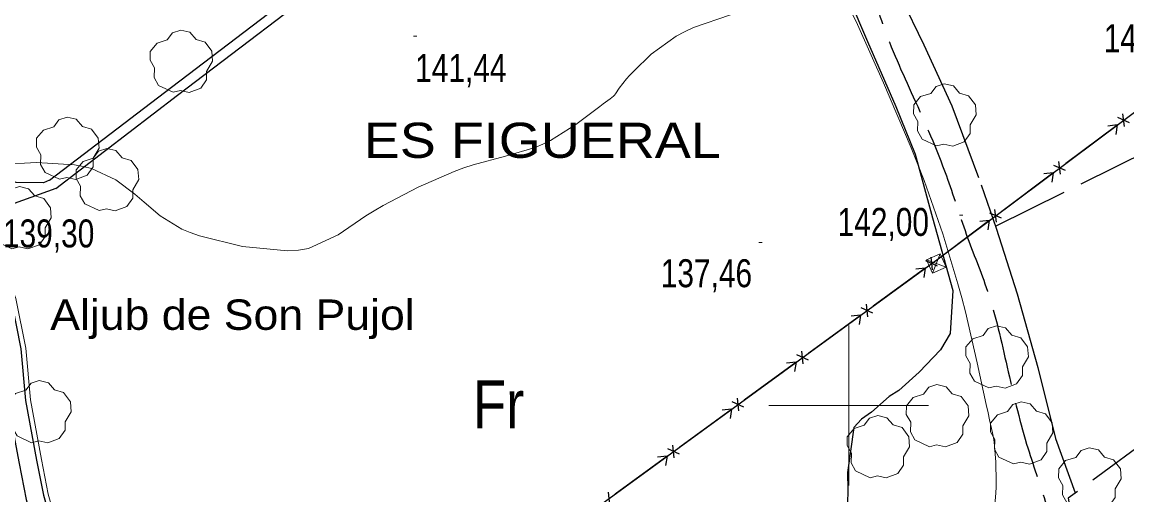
# Model space of a CAD drawing. Extents: x -807245 to 6129983, y -54972206 to 262146364.
# Drawn here: x 488741 to 489087.2, y 4383472 to 4383619.9 of the extents above; entities that cross this region are included whole.
import ezdxf
from ezdxf.enums import TextEntityAlignment as Align

# ---------------------------------------------------------------- set-up
doc = ezdxf.new("R2010")
doc.units = 0
doc.header["$LTSCALE"] = 4
doc.linetypes.add('LONG_DASHED', pattern=[7.5, 6, -1.5])
for name, color, linetype, lineweight in [('1', 7, 'Continuous', 13), ('25', 7, 'LONG_DASHED', 25), ('27', 7, 'Continuous', 25), ('29', 7, 'Continuous', 13), ('36', 7, 'Continuous', 25), ('38', 7, 'Continuous', 25), ('43', 7, 'Continuous', 25), ('51', 7, 'Continuous', 13), ('7', 7, 'Continuous', 13), ('9', 7, 'Continuous', 13)]:
    doc.layers.add(name, color=color, linetype=linetype, lineweight=lineweight)
doc.layers.add('31', color=7, linetype='Continuous')
doc.layers.add('5', color=7, linetype='Continuous')

msp = doc.modelspace()

# ---------------------------------------------------------------- linework, layer by layer
at = {"layer": '1'}
for p, q in [((489000, 4383525), (489000, 4383475)), ((488975, 4383500), (489025, 4383500))]:
    msp.add_line(p, q, dxfattribs=at)
at = {"layer": '25'}
msp.add_line((489045.94, 4383556.09), (489152.62, 4383608.65), dxfattribs=at)
for points in [[(489064.84, 4383687.92), (489050.6, 4383701.9), (489044.09, 4383702.72), (489041.35, 4383706.35), (489037.89, 4383712.32), (489035.25, 4383717.83), (489031.19, 4383723.35), (488971.86, 4383711.2), (488971.58, 4383706.47), (488982.99, 4383687.44), (488994.03, 4383668.18), (489007.57, 4383645.07), (489016.3, 4383627.79), (489023.56, 4383612.78), (489032.27, 4383593.77), (489041.51, 4383568.99), (489046.16, 4383555.43), (489052.75, 4383534.95), (489059.24, 4383511.84), (489064.77, 4383489.72), (489070.99, 4383472.64)], [(488997.32, 4383634.23), (489005.86, 4383613.88), (489014.71, 4383593.52), (489020.84, 4383578.6), (489026.24, 4383558.66), (489032.66, 4383536), (489031.76, 4383522.51), (489028.77, 4383517.44), (489022.02, 4383510.47), (489015.72, 4383504.69), (489012.63, 4383502.77), (489007.17, 4383497.88), (489003.99, 4383495.67), (489001.56, 4383493.07), (488999.6, 4383479.06), (488999.69, 4383473.74), (488999.64, 4383469.08), (488999.45, 4383465.86), (488999.4, 4383461.28), (489002.78, 4383448.12), (489005.3, 4383445.61), (489006.19, 4383444.78), (489011.29, 4383437.82), (489016.89, 4383429.35)], [(489240.47, 4383481.68), (489167.79, 4383431.69), (489119.98, 4383508.68), (489068.76, 4383471), (489070.95, 4383459.27), (489077.91, 4383424.98), (489081.71, 4383402.66), (489085.82, 4383375.15), (489086.67, 4383350.61), (489087.73, 4383318.64), (489087.36, 4383306.34), (489106.74, 4383317.1)]]:
    msp.add_lwpolyline(points, dxfattribs=at)
at = {"layer": '27'}
msp.add_spline([(491255.21, 4383970.03), (491244.34, 4383967.52), (491230.36, 4383957.66), (491230.81, 4383957.81), (491230.81, 4383957.81), (491220.15, 4383951.47), (491212.7, 4383943.01), (491205.06, 4383944.23), (491184.85, 4383957.71), (491152.82, 4383981.27), (491128.36, 4384004.58), (491128.29, 4384004.88), (491122.26, 4384021.39), (491095.75, 4384034.59), (491071.07, 4384059.32), (491064.71, 4384065.12)], degree=3, dxfattribs=at)
at = {"layer": '29'}
for points in [[(488788.32, 4383597.98), (488783.78, 4383600.1), (488782.37, 4383602.64), (488782.47, 4383605.62), (488781.1, 4383608.03), (488781.14, 4383610.78), (488783.3, 4383613.38), (488786.49, 4383614.38), (488788.14, 4383616.57), (488790.71, 4383617.4), (488793.57, 4383616.75), (488795.52, 4383614.48), (488798.33, 4383613.66), (488800.46, 4383610.81), (488800.7, 4383607.68), (488798.82, 4383604.53), (488798.82, 4383601.85), (488797, 4383599.24), (488793.38, 4383597.9), (488790.61, 4383598.53)], [(489027.53, 4383581.23), (489022.99, 4383583.35), (489021.58, 4383585.89), (489021.68, 4383588.87), (489020.31, 4383591.28), (489020.35, 4383594.03), (489022.51, 4383596.63), (489025.7, 4383597.63), (489027.35, 4383599.82), (489029.92, 4383600.65), (489032.78, 4383600), (489034.73, 4383597.73), (489037.54, 4383596.91), (489039.67, 4383594.06), (489039.91, 4383590.93), (489038.03, 4383587.78), (489038.03, 4383585.1), (489036.21, 4383582.49), (489032.59, 4383581.15), (489029.82, 4383581.78)], [(488752.75, 4383570.78), (488748.21, 4383572.9), (488746.8, 4383575.44), (488746.9, 4383578.42), (488745.53, 4383580.83), (488745.57, 4383583.58), (488747.73, 4383586.18), (488750.92, 4383587.18), (488752.57, 4383589.37), (488755.14, 4383590.2), (488758, 4383589.55), (488759.95, 4383587.28), (488762.76, 4383586.46), (488764.89, 4383583.61), (488765.13, 4383580.48), (488763.25, 4383577.33), (488763.25, 4383574.65), (488761.43, 4383572.04), (488757.81, 4383570.7), (488755.04, 4383571.33)], [(488765.17, 4383560.96), (488760.63, 4383563.08), (488759.22, 4383565.62), (488759.32, 4383568.6), (488757.95, 4383571.01), (488757.99, 4383573.76), (488760.15, 4383576.36), (488763.34, 4383577.36), (488764.99, 4383579.55), (488767.56, 4383580.38), (488770.42, 4383579.73), (488772.37, 4383577.46), (488775.18, 4383576.64), (488777.31, 4383573.79), (488777.55, 4383570.66), (488775.67, 4383567.51), (488775.67, 4383564.83), (488773.85, 4383562.22), (488770.23, 4383560.88), (488767.46, 4383561.51)], [(488737.8, 4383549.04), (488733.26, 4383551.16), (488731.85, 4383553.7), (488731.95, 4383556.68), (488730.58, 4383559.09), (488730.62, 4383561.84), (488732.78, 4383564.44), (488735.97, 4383565.44), (488737.62, 4383567.63), (488740.19, 4383568.46), (488743.05, 4383567.81), (488745, 4383565.54), (488747.81, 4383564.72), (488749.94, 4383561.87), (488750.18, 4383558.74), (488748.3, 4383555.59), (488748.3, 4383552.91), (488746.48, 4383550.3), (488742.86, 4383548.96), (488740.09, 4383549.59)], [(489043.92, 4383505.5), (489039.38, 4383507.62), (489037.97, 4383510.16), (489038.07, 4383513.14), (489036.7, 4383515.55), (489036.74, 4383518.3), (489038.9, 4383520.9), (489042.09, 4383521.9), (489043.74, 4383524.09), (489046.31, 4383524.92), (489049.17, 4383524.27), (489051.12, 4383522), (489053.93, 4383521.18), (489056.06, 4383518.33), (489056.3, 4383515.2), (489054.42, 4383512.05), (489054.42, 4383509.37), (489052.6, 4383506.76), (489048.98, 4383505.42), (489046.21, 4383506.05)], [(488744.01, 4383488.36), (488739.47, 4383490.48), (488738.06, 4383493.02), (488738.16, 4383496), (488736.79, 4383498.41), (488736.83, 4383501.16), (488738.99, 4383503.76), (488742.18, 4383504.76), (488743.83, 4383506.95), (488746.4, 4383507.78), (488749.26, 4383507.13), (488751.21, 4383504.86), (488754.02, 4383504.04), (488756.15, 4383501.19), (488756.39, 4383498.06), (488754.51, 4383494.91), (488754.51, 4383492.23), (488752.69, 4383489.62), (488749.07, 4383488.28), (488746.3, 4383488.91)], [(489025.26, 4383487.11), (489020.72, 4383489.23), (489019.31, 4383491.77), (489019.41, 4383494.75), (489018.04, 4383497.16), (489018.08, 4383499.91), (489020.24, 4383502.51), (489023.43, 4383503.51), (489025.08, 4383505.7), (489027.65, 4383506.53), (489030.51, 4383505.88), (489032.46, 4383503.61), (489035.27, 4383502.79), (489037.4, 4383499.94), (489037.64, 4383496.81), (489035.76, 4383493.66), (489035.76, 4383490.98), (489033.94, 4383488.37), (489030.32, 4383487.03), (489027.55, 4383487.66)], [(489051.6, 4383481.7), (489047.06, 4383483.82), (489045.65, 4383486.36), (489045.75, 4383489.34), (489044.38, 4383491.75), (489044.42, 4383494.5), (489046.58, 4383497.1), (489049.77, 4383498.1), (489051.42, 4383500.29), (489053.99, 4383501.12), (489056.85, 4383500.47), (489058.8, 4383498.2), (489061.61, 4383497.38), (489063.74, 4383494.53), (489063.98, 4383491.4), (489062.1, 4383488.25), (489062.1, 4383485.57), (489060.28, 4383482.96), (489056.66, 4383481.62), (489053.89, 4383482.25)], [(489006.69, 4383477.41), (489002.15, 4383479.53), (489000.74, 4383482.07), (489000.84, 4383485.05), (488999.47, 4383487.46), (488999.51, 4383490.21), (489001.67, 4383492.81), (489004.86, 4383493.81), (489006.51, 4383496), (489009.08, 4383496.83), (489011.94, 4383496.18), (489013.89, 4383493.91), (489016.7, 4383493.09), (489018.83, 4383490.24), (489019.07, 4383487.11), (489017.19, 4383483.96), (489017.19, 4383481.28), (489015.37, 4383478.67), (489011.75, 4383477.33), (489008.98, 4383477.96)], [(489072.97, 4383467.36), (489068.43, 4383469.48), (489067.02, 4383472.02), (489067.12, 4383475), (489065.75, 4383477.41), (489065.79, 4383480.16), (489067.95, 4383482.76), (489071.14, 4383483.76), (489072.79, 4383485.95), (489075.36, 4383486.78), (489078.22, 4383486.13), (489080.17, 4383483.86), (489082.98, 4383483.04), (489085.11, 4383480.19), (489085.35, 4383477.06), (489083.47, 4383473.91), (489083.47, 4383471.23), (489081.65, 4383468.62), (489078.03, 4383467.28), (489075.26, 4383467.91)]]:
    msp.add_lwpolyline(points, close=True, dxfattribs=at)
at = {"layer": '36'}
for points in [[(488701.67, 4383601.03), (488713.18, 4383583.78), (488720.76, 4383571.83), (488727.27, 4383559.98), (488731.21, 4383549.93), (488737.55, 4383533.06), (488740.6, 4383517.68), (488742.06, 4383501.51), (488745.58, 4383482.85), (488747.68, 4383471.91), (488751.03, 4383460.11), (488755.94, 4383445.19), (488763.36, 4383423.37), (488769.52, 4383401.51), (488775.12, 4383378.28), (488779.4, 4383360.18), (488784.4, 4383341.28), (488787.42, 4383323.42), (488790.51, 4383309.68), (488792.66, 4383293.05), (488794.73, 4383278.89), (488796.8, 4383269.66)], [(488697.56, 4383598.21), (488708.51, 4383580.77), (488715.97, 4383569), (488722.23, 4383557.62), (488726.02, 4383547.94), (488732.19, 4383531.54), (488735.09, 4383516.88), (488736.55, 4383500.75), (488740.12, 4383481.81), (488742.27, 4383470.62), (488745.71, 4383458.48), (488750.67, 4383443.42), (488758.05, 4383421.72), (488764.14, 4383400.1), (488769.72, 4383376.99), (488774.01, 4383358.83), (488778.96, 4383340.1), (488781.97, 4383322.35), (488785.03, 4383308.71), (488787.15, 4383292.29), (488789.26, 4383277.88), (488791.34, 4383268.61)]]:
    msp.add_lwpolyline(points, dxfattribs=at)
at = {"layer": '38'}
msp.add_line((488751.62, 4383567.92), (488727.54, 4383559.3), dxfattribs=at)
for points in [[(488751.62, 4383567.92), (488789.76, 4383597.05), (488843.03, 4383637.6), (488887.89, 4383679.96), (488895.08, 4383687.46), (488898.54, 4383694.17), (488901.86, 4383699.2), (488905.38, 4383705.28), (488906.3, 4383707.26), (488907.87, 4383708.98), (488910.28, 4383710.27), (488911.71, 4383710.66), (488914.41, 4383711.57), (488928.26, 4383713.8), (488964.77, 4383720.59), (489019.58, 4383732.51), (489043.43, 4383738.69), (489051.39, 4383740.35), (489055.38, 4383740.31), (489059.3, 4383739.22), (489062.91, 4383737.71), (489067.01, 4383734.96), (489070.32, 4383730.1)], [(488749.66, 4383570.48), (488787.8, 4383599.61), (488840.94, 4383640.07), (488885.62, 4383682.25), (488892.43, 4383689.35), (488895.75, 4383695.8), (488899.12, 4383700.9), (488902.52, 4383706.76), (488903.58, 4383709.06), (488905.86, 4383711.56), (488909.08, 4383713.29), (488910.77, 4383713.75), (488913.63, 4383714.71), (488927.71, 4383716.98), (488952.22, 4383721.54)], [(488749.66, 4383570.48), (488747.74, 4383569.7), (488739.18, 4383569.8), (488734.92, 4383571.12), (488726.18, 4383574.08), (488721.92, 4383575.62), (488715.87, 4383579.53)]]:
    msp.add_lwpolyline(points, dxfattribs=at)
at = {"layer": '38', "linetype": 'LONG_DASHED'}
msp.add_spline([(488955.84, 4383718.93), (488982.19, 4383676.49), (488994.16, 4383653.7), (489004.69, 4383635.88), (489010.58, 4383619.45), (489020.22, 4383596.54), (489030.59, 4383571.89), (489036.84, 4383553.59), (489043.46, 4383535.81), (489049.64, 4383512.03), (489055.75, 4383487.95), (489061.98, 4383468.82), (489067.02, 4383449.79), (489070.82, 4383428.51), (489074.72, 4383407.91), (489078.13, 4383385.07), (489080.63, 4383367.11), (489082.86, 4383338.57), (489084.43, 4383298.57), (489086.67, 4383251.81), (489090.1, 4383204.28), (489089.96, 4383184.77)], degree=3, dxfattribs=at)
at = {"layer": '43'}
for p, q in [((489087.96, 4383588.47), (489084.29, 4383590.05)), ((489086.36, 4383587.27), (489085.89, 4383591.24)), ((489068, 4383575.76), (489084.03, 4383587.72)), ((489084.12, 4383587.77), (489081.14, 4383587.42)), ((489084.12, 4383587.77), (489083.68, 4383584.81)), ((489067.92, 4383573.52), (489064.25, 4383575.1)), ((489066.32, 4383572.33), (489065.85, 4383576.3)), ((489047.96, 4383560.81), (489063.99, 4383572.77)), ((489064.08, 4383572.83), (489061.1, 4383572.47)), ((489064.08, 4383572.83), (489063.64, 4383569.86)), ((489046.28, 4383557.38), (489045.81, 4383561.35)), ((489044.04, 4383557.88), (489041.06, 4383557.53)), ((489044.04, 4383557.88), (489043.61, 4383554.91)), ((489047.88, 4383558.58), (489044.21, 4383560.15)), ((489026.2, 4383542.46), (489025.78, 4383546.43)), ((489007.7, 4383531.15), (489023.87, 4383542.92)), ((489023.96, 4383542.98), (489020.98, 4383542.66)), ((489023.96, 4383542.98), (489023.49, 4383540.02)), ((489027.82, 4383543.63), (489024.16, 4383545.25)), ((489007.6, 4383528.93), (489003.95, 4383530.55)), ((489005.98, 4383527.75), (489005.56, 4383531.72)), ((488987.49, 4383516.45), (489003.66, 4383528.21)), ((489003.74, 4383528.27), (489000.76, 4383527.96)), ((489003.74, 4383528.27), (489003.28, 4383525.31)), ((488987.38, 4383514.22), (488983.73, 4383515.84)), ((488985.76, 4383513.04), (488985.35, 4383517.02)), ((488967.28, 4383501.75), (488983.45, 4383513.51)), ((488983.53, 4383513.57), (488980.54, 4383513.25)), ((488983.53, 4383513.57), (488983.06, 4383510.61)), ((488965.55, 4383498.34), (488965.13, 4383502.31)), ((488947.07, 4383487.05), (488963.24, 4383498.81)), ((488963.31, 4383498.86), (488960.33, 4383498.55)), ((488963.31, 4383498.86), (488962.84, 4383495.9)), ((488967.16, 4383499.51), (488963.51, 4383501.14)), ((488945.33, 4383483.63), (488944.91, 4383487.61)), ((488926.86, 4383472.35), (488943.03, 4383484.11)), ((488943.09, 4383484.16), (488940.11, 4383483.84)), ((488943.09, 4383484.16), (488942.63, 4383481.19)), ((488946.95, 4383484.81), (488943.29, 4383486.43)), ((488925.11, 4383468.92), (488924.69, 4383472.9))]:
    msp.add_line(p, q, dxfattribs=at)
at = {"layer": '43', "lineweight": 13}
for p, q in [((489026.21, 4383541.42), (489028.69, 4383547.44)), ((489024.39, 4383545.54), (489030.51, 4383543.32))]:
    msp.add_line(p, q, dxfattribs=at)
at = {"layer": '43'}
for points in [[(488001.89, 4382789.17), (488218.68, 4382951.32), (488457.31, 4383127.02), (488717.97, 4383320.4), (489027.99, 4383545.91), (489266.87, 4383724.08), (489744.68, 4384077.94)], [(489027.92, 4383545.86), (489027.99, 4383545.91), (489043.95, 4383557.82)]]:
    msp.add_lwpolyline(points, dxfattribs=at)
at = {"layer": '43', "lineweight": 13}
msp.add_lwpolyline([(489026.21, 4383541.42), (489024.39, 4383545.54), (489028.69, 4383547.44), (489030.51, 4383543.32)], close=True, dxfattribs=at)
at = {"layer": '51'}
msp.add_lwpolyline([(488731.39, 4383553.76), (488732.67, 4383550.49), (488739.06, 4383533.49), (488742.15, 4383517.9), (488743.61, 4383501.73), (488747.12, 4383483.14), (488749.2, 4383472.27), (488752.53, 4383460.57), (488757.42, 4383445.69), (488764.86, 4383423.83), (488771.03, 4383401.91), (488776.64, 4383378.64), (488780.92, 4383360.56), (488785.93, 4383341.61), (488788.96, 4383323.72), (488792.05, 4383309.95), (488794.21, 4383293.26), (488796.27, 4383279.17), (488798.34, 4383269.95)], dxfattribs=at)
at = {"layer": '7'}
for p, q in [((488863.67, 4383615.57), (488864.67, 4383615.57)), ((489034.75, 4383559.53), (489035.75, 4383559.53)), ((488971.86, 4383550.94), (488972.86, 4383550.94))]:
    msp.add_line(p, q, dxfattribs=at)
at = {"layer": '9'}
for points in [[(489045.52, 4383466.12), (489046.11, 4383472.64), (489046.18, 4383474.4), (489046.23, 4383476.15), (489046.07, 4383482.3), (489045.69, 4383487.37), (489045.58, 4383488.44), (489045.47, 4383489.35), (489045.09, 4383491.44), (489044.12, 4383495.5), (489043.64, 4383497.65), (489043.07, 4383500.26), (489040.27, 4383513.39), (489036.56, 4383529.34), (489035.42, 4383533.72), (489034.23, 4383538.08), (489029.52, 4383553.69), (489023.61, 4383570.37), (489021.66, 4383575.4), (489019.57, 4383580.62), (489010.9, 4383600.96), (489002.71, 4383619.18), (489000.92, 4383623.05)], [(488962.93, 4383622.19), (488951.33, 4383618.22), (488948.54, 4383616.93), (488945.94, 4383615.55), (488938.11, 4383609.88), (488932.54, 4383604.47), (488931.37, 4383603.25), (488930.37, 4383602.16), (488928.08, 4383599.25), (488926.9, 4383597.46), (488926.59, 4383597.07), (488926.3, 4383596.73), (488925.3, 4383595.89), (488923.07, 4383594.34), (488922, 4383593.55), (488920.73, 4383592.61), (488914.49, 4383587.88), (488906.54, 4383582.87), (488904.18, 4383581.75), (488901.76, 4383580.73), (488892.47, 4383578.02), (488882.36, 4383575.33), (488879.42, 4383574.33), (488876.42, 4383573.22)], [(488876.42, 4383573.22), (488865.08, 4383568.28), (488854.11, 4383562.55), (488851.34, 4383560.93), (488848.69, 4383559.31), (488840.08, 4383553.36), (488830.71, 4383549.14), (488827.58, 4383548.61), (488824.21, 4383548.35), (488810.11, 4383549.71), (488796.64, 4383553.1), (488793.67, 4383554.12), (488791.03, 4383555.18), (488784.26, 4383559.28), (488779.32, 4383563.65), (488777.84, 4383564.88), (488776.32, 4383566.1), (488770.4, 4383570.58), (488762.8, 4383574.15), (488760.21, 4383574.81), (488757.41, 4383575.32), (488745.55, 4383575.98), (488734.04, 4383575.36)]]:
    msp.add_lwpolyline(points, dxfattribs=at)

# ---------------------------------------------------------------- texts
at = {"layer": '31', "width": 0.85}
msp.add_text('Fr', height=15, dxfattribs=at).set_placement((488890.3, 4383492.9), align=Align.CENTER)
at = {"layer": '5'}
for s, height, width, p in [('ES FIGUERAL', 11, 1.15, (488959.94, 4383577.47)), ('Aljub de Son Pujol', 9.5, 1.1, (488864.03, 4383523.66))]:
    msp.add_text(s, height=height, dxfattribs=dict(at, width=width)).set_placement(p, align=Align.RIGHT)
at = {"layer": '7', "width": 0.8}
for s, p in [('140,19', (489079.89, 4383610.52)), ('141,44', (488864.17, 4383601.2)), ('142,00', (488996.52, 4383553.05)), ('139,30', (488735.03, 4383549.45)), ('137,46', (488941.1, 4383537))]:
    msp.add_text(s, height=8.75, dxfattribs=at).set_placement(p)

doc.saveas('drawing.dxf')
